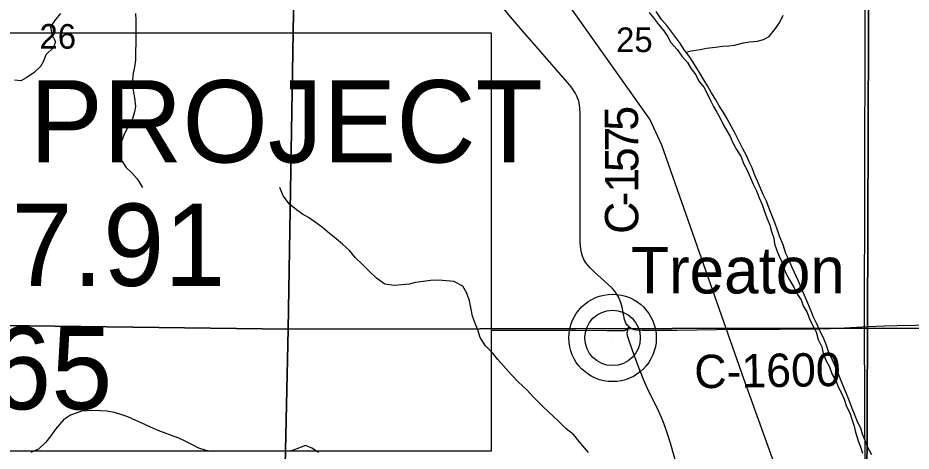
# Model space of a CAD drawing. Extents: x 0 to 34, y 0 to 22.
# Drawn here: x 17.64 to 19.16, y 14.964 to 15.701 of the extents above; entities that cross this region are included whole.
import ezdxf

# ---------------------------------------------------------------- set-up
doc = ezdxf.new("R2010")
doc.units = 0
for name, color, linetype in [('GM_X_County_Road', 7, 'Continuous'), ('GM_X_County_Road_Text', 7, 'Continuous'), ('GM_X_Major_River', 7, 'Continuous'), ('GM_X_Minor_River', 7, 'Continuous'), ('GM_X_Rail_Line', 7, 'Continuous'), ('GM_X_Section', 7, 'Continuous'), ('GM_X_Section_Text', 7, 'Continuous'), ('GM_X_Township_Road', 7, 'Continuous'), ('GM_X_Unincorporated', 7, 'Continuous'), ('GM_X_Unincorporated_Location', 7, 'Continuous'), ('GM_X_Unincorporated_Text', 7, 'Continuous'), ('GM_X_US_Shield', 7, 'Continuous'), ('SH_Text', 7, 'Continuous')]:
    doc.layers.add(name, color=color, linetype=linetype)

msp = doc.modelspace()

# ---------------------------------------------------------------- linework, layer by layer
at = {"layer": 'GM_X_County_Road'}
for points in [[(18.6801, 15.1752), (18.6769, 15.1782), (18.6747, 15.1812), (18.6733, 15.1847), (18.6726, 15.1876), (18.6707, 15.1967), (18.6681, 15.2089), (18.6665, 15.2148), (18.6645, 15.2206), (18.6619, 15.2262), (18.6588, 15.2314), (18.6552, 15.2363), (18.6511, 15.2409), (18.6444, 15.2473), (18.6213, 15.2681), (18.6146, 15.2747), (18.6103, 15.2793), (18.6065, 15.2843), (18.6048, 15.287), (18.6032, 15.2897), (18.6018, 15.2926), (18.6007, 15.2955), (18.599, 15.3016), (18.5978, 15.3078), (18.597, 15.3184), (18.5969, 15.3261), (18.5968, 15.3359), (18.5968, 15.3488), (18.5968, 15.3607), (18.5968, 15.37), (18.5967, 15.3948), (18.5969, 15.4228), (18.5969, 15.4508), (18.5967, 15.4819), (18.5971, 15.5253), (18.5968, 15.5377), (18.5963, 15.547), (18.5956, 15.5531), (18.5944, 15.5591), (18.5935, 15.562), (18.5912, 15.5677), (18.5884, 15.5731), (18.5852, 15.5784), (18.5816, 15.5834), (18.5757, 15.5905), (18.5634, 15.6044), (18.5226, 15.6514), (18.5022, 15.6748), (18.4819, 15.6984), (18.4578, 15.7268)], [(19.0861, 15.1755), (19.1151, 15.1769), (19.1368, 15.1775), (19.1679, 15.1781), (19.1866, 15.1784), (19.2239, 15.1785), (19.2425, 15.1784), (19.286, 15.1781), (19.3202, 15.1776), (19.3886, 15.1766), (19.4477, 15.1761), (19.5782, 15.1751), (19.6217, 15.1747), (19.6435, 15.1744), (19.6838, 15.1737), (19.718, 15.1739)], [(18.6801, 15.1752), (18.6841, 15.1726), (18.6885, 15.1709), (18.6923, 15.1701), (18.7023, 15.1694), (18.7185, 15.1695), (18.7613, 15.1694), (18.7955, 15.1698), (18.8288, 15.1704), (18.8857, 15.1711), (18.9158, 15.1714), (18.937, 15.1714), (18.9566, 15.1717), (19.0033, 15.172), (19.022, 15.1724), (19.0468, 15.1734), (19.0778, 15.1751), (19.0861, 15.1755)]]:
    msp.add_lwpolyline(points, dxfattribs=at)
at = {"layer": 'GM_X_Major_River'}
for points in [[(18.7142, 15.7102), (18.7218, 15.7007), (18.73, 15.6896), (18.7391, 15.6789), (18.7459, 15.6686), (18.7515, 15.6591), (18.762, 15.6473), (18.77, 15.6359), (18.7794, 15.6248), (18.7858, 15.6142), (18.7937, 15.6039), (18.7989, 15.5932), (18.808, 15.5825), (18.8188, 15.5605), (18.8241, 15.5502), (18.8297, 15.5403), (18.835, 15.53), (18.8406, 15.5193), (18.8466, 15.5087), (18.8523, 15.4988), (18.8568, 15.4885), (18.8631, 15.4767), (18.8707, 15.4642), (18.8748, 15.4531), (18.8804, 15.4428), (18.8868, 15.4288), (18.8916, 15.4177), (18.8973, 15.4067), (18.9014, 15.3945), (18.9066, 15.3835), (18.9104, 15.3732), (18.9149, 15.3607), (18.9197, 15.3481), (18.9227, 15.3375), (18.9264, 15.3261), (18.9279, 15.3166), (18.9316, 15.3048), (18.9354, 15.2953), (18.9402, 15.2858), (18.9432, 15.2763), (18.9477, 15.2656), (18.953, 15.255), (18.9612, 15.2416), (18.9661, 15.231), (18.9729, 15.2211), (18.9766, 15.2108), (18.9834, 15.1994), (18.9875, 15.1887), (18.9924, 15.1781), (18.9988, 15.1667), (19.0021, 15.1537), (19.0081, 15.1412), (19.0107, 15.1298), (19.0152, 15.1184), (19.0216, 15.107), (19.0257, 15.094), (19.0328, 15.0826), (19.0362, 15.0731), (19.0414, 15.0636), (19.0463, 15.0522), (19.0504, 15.0396), (19.0557, 15.029), (19.0594, 15.0179), (19.0631, 15.0062), (19.0657, 14.9959), (19.0702, 14.9811), (19.0739, 14.9708), (19.0773, 14.9605)], [(19.0934, 14.9572), (19.0865, 14.9697), (19.0831, 14.9792), (19.0778, 14.9928), (19.0747, 15.0027), (19.0693, 15.0137), (19.0651, 15.0239), (19.0598, 15.0364), (19.0541, 15.0516), (19.0491, 15.0641), (19.0449, 15.0747), (19.0392, 15.0891), (19.0331, 15.1035), (19.0262, 15.1186), (19.0197, 15.133), (19.0155, 15.1451), (19.0105, 15.1577), (19.0056, 15.1675), (18.9991, 15.1815), (18.9941, 15.1917), (18.9903, 15.2016), (18.9842, 15.2152), (18.9788, 15.2285), (18.9735, 15.2402), (18.9685, 15.2528), (18.9571, 15.277), (18.9521, 15.2899), (18.9471, 15.3001), (18.9422, 15.3145), (18.9364, 15.3293), (18.9326, 15.3399), (18.9288, 15.3509), (18.923, 15.3649), (18.9185, 15.3767), (18.9139, 15.3888), (18.9081, 15.4013), (18.9039, 15.4111), (18.8986, 15.4229), (18.8936, 15.4346), (18.8898, 15.4456), (18.8848, 15.4559), (18.8803, 15.4665), (18.8738, 15.4778), (18.8665, 15.4926), (18.8612, 15.5032), (18.8543, 15.5157), (18.8471, 15.529), (18.841, 15.5396), (18.8337, 15.5513), (18.8276, 15.5612), (18.8204, 15.5733), (18.8135, 15.585), (18.8074, 15.5956), (18.8002, 15.6077), (18.7914, 15.6214), (18.7823, 15.6354), (18.7747, 15.6456), (18.7663, 15.6585), (18.7564, 15.6721), (18.7442, 15.688), (18.7354, 15.6978), (18.7263, 15.7115)]]:
    msp.add_lwpolyline(points, dxfattribs=at)
at = {"layer": 'GM_X_Minor_River'}
for points in [[(17.7124, 15.7083), (17.7037, 15.6981), (17.695, 15.6859), (17.6973, 15.6719), (17.7034, 15.6609), (17.7, 15.6503), (17.6872, 15.6377), (17.683, 15.6274), (17.6781, 15.6179), (17.6675, 15.608), (17.655, 15.5993), (17.6444, 15.5936), (17.6338, 15.595)], [(17.8398, 15.7084), (17.8406, 15.697), (17.8407, 15.6712), (17.8403, 15.6571), (17.84, 15.6439), (17.8397, 15.6291), (17.8382, 15.6177), (17.8359, 15.6067), (17.8341, 15.59), (17.836, 15.5771), (17.8383, 15.5649), (17.8399, 15.5501), (17.8384, 15.5407), (17.835, 15.5289), (17.826, 15.5141), (17.8199, 15.5015), (17.8158, 15.4901), (17.8139, 15.478), (17.8151, 15.4658), (17.817, 15.4564), (17.8239, 15.4465), (17.8338, 15.4371), (17.8425, 15.4268), (17.8517, 15.4125)], [(18.777, 15.6424), (18.786, 15.6449), (18.8012, 15.6468), (18.8122, 15.6491), (18.8274, 15.6511), (18.8391, 15.6526), (18.8501, 15.6534), (18.8596, 15.6546), (18.8748, 15.6581), (18.8854, 15.66), (18.8987, 15.6612), (18.9089, 15.6639), (18.9187, 15.6692), (18.9297, 15.6825), (18.9361, 15.6924), (18.9425, 15.7057)], [(18.6109, 14.9614), (18.598, 14.9765), (18.5858, 14.9917), (18.5732, 15.0019), (18.5607, 15.014), (18.5508, 15.0231), (18.534, 15.039), (18.5181, 15.0548), (18.5063, 15.0677), (18.4918, 15.0813), (18.4796, 15.0942), (18.4663, 15.1089), (18.4568, 15.1195), (18.4481, 15.1305), (18.4355, 15.143), (18.4267, 15.157), (18.4229, 15.1699), (18.4187, 15.1797), (18.4137, 15.1934), (18.4114, 15.2051), (18.4087, 15.2192), (18.4041, 15.2324), (18.3969, 15.2442), (18.3817, 15.2521), (18.3692, 15.2532), (18.3555, 15.2543), (18.3422, 15.2542), (18.3297, 15.2523), (18.3165, 15.2504), (18.3055, 15.2477), (18.2933, 15.2465), (18.2801, 15.2453), (18.2641, 15.2475), (18.2504, 15.2581), (18.2383, 15.2691), (18.2261, 15.2812), (18.2143, 15.2925), (18.2044, 15.305), (18.1922, 15.316), (18.1816, 15.3247), (18.1702, 15.3341), (18.1584, 15.344), (18.1458, 15.3534), (18.1344, 15.3613), (18.1242, 15.367), (18.1139, 15.3742), (18.1021, 15.3836), (18.0911, 15.398), (18.0857, 15.412)], [(17.971, 14.9632), (17.96, 14.9647), (17.9478, 14.9688), (17.936, 14.9749), (17.9235, 14.9813), (17.9136, 14.9858), (17.8996, 14.9911), (17.8878, 14.9952), (17.8783, 14.9986), (17.8654, 15.0043), (17.8532, 15.0103), (17.8407, 15.0159), (17.8267, 15.022), (17.8168, 15.0257), (17.8039, 15.0295), (17.7913, 15.0317), (17.78, 15.0321), (17.7671, 15.0328), (17.7576, 15.0324), (17.7481, 15.0316), (17.7386, 15.0285), (17.7292, 15.0251), (17.7174, 15.0167), (17.7034, 15.0011), (17.6959, 14.9897), (17.6872, 14.9787), (17.6747, 14.9672), (17.6614, 14.9615)], [(18.1512, 14.9615), (18.1398, 14.9687), (18.1295, 14.9732), (18.1147, 14.9675), (18.1018, 14.9633)]]:
    msp.add_lwpolyline(points, dxfattribs=at)
at = {"layer": 'GM_X_Rail_Line'}
for points in [[(19.082, 14.1642), (19.0858, 15.176), (19.0896, 16.1806), (19.0934, 17.1717), (19.0972, 18.1277), (19.0975, 18.2511), (19.0976, 18.2716), (19.1032, 19.1112), (19.1046, 20.1073), (19.105, 20.2214), (18.9873, 20.2214), (18.4948, 20.2275), (17.7586, 20.2281), (16.9636, 20.2311)], [(19.1602, 14.2954), (18.8757, 15.0866), (18.7358, 15.4844), (18.7152, 15.5285), (18.5866, 15.7098), (18.3527, 16.0317), (18.2813, 16.1295), (18.2071, 16.1856), (18.119, 16.2347), (17.9168, 16.34), (17.6261, 16.4909)]]:
    msp.add_lwpolyline(points, dxfattribs=at)
msp.add_lwpolyline([(20.0404, 14.169), (20.0404, 20.2202), (19.5489, 20.2208), (19.5137, 20.2208), (19.105, 20.2214), (19.1046, 20.1073), (19.1032, 19.1112), (19.0976, 18.2716), (19.0975, 18.2511), (19.0972, 18.1277), (19.0934, 17.1717), (19.0896, 16.1806), (19.0858, 15.176), (19.082, 14.1642)], close=True, dxfattribs=at)
at = {"layer": 'GM_X_Section'}
for points in [[(17.0958, 16.189), (18.1169, 16.1822), (18.0996, 15.1714), (17.0854, 15.1843)], [(19.0829, 16.1788), (19.0804, 15.1729), (18.0996, 15.1714), (18.1169, 16.1822)], [(17.0854, 15.1843), (18.0996, 15.1714), (18.0777, 14.1666), (17.1558, 14.1702), (17.0728, 14.1742)], [(18.0996, 15.1714), (19.0804, 15.1729), (19.0847, 14.1682), (18.1505, 14.1672), (18.0777, 14.1666)]]:
    msp.add_lwpolyline(points, close=True, dxfattribs=at)
at = {"layer": 'GM_X_Township_Road'}
for points in [[(18.4454, 15.1696), (18.4466, 15.1695), (18.4745, 15.1694), (18.5429, 15.1693), (18.5894, 15.1693), (18.6424, 15.1689), (18.6534, 15.1691), (18.6648, 15.169), (18.6722, 15.1692), (18.675, 15.1704), (18.6778, 15.1723), (18.6801, 15.1752)], [(18.7645, 14.9293), (18.7505, 14.977), (18.7449, 14.9947), (18.7398, 15.0093), (18.7352, 15.0208), (18.7301, 15.0321), (18.7112, 15.0713), (18.7049, 15.0855), (18.6944, 15.1115), (18.6857, 15.1348), (18.6791, 15.1545), (18.6776, 15.1599), (18.6769, 15.164), (18.6773, 15.168), (18.6784, 15.1715), (18.6801, 15.1752)]]:
    msp.add_lwpolyline(points, dxfattribs=at)
at = {"layer": 'GM_X_Unincorporated'}
for radius in [0.0744, 0.0472]:
    msp.add_circle((18.652, 15.1563), radius, dxfattribs=at)
at = {"layer": 'GM_X_Unincorporated_Location'}
msp.add_line((18.652, 15.1563), (18.652, 15.1563), dxfattribs=at)
at = {"layer": 'GM_X_US_Shield'}
for points in [[(20.0404, 15.1674), (20.0404, 16.173), (19.0829, 16.1788), (19.0804, 15.1729)], [(20.0404, 14.1653), (20.0404, 15.1674), (19.0804, 15.1729), (19.0847, 14.1682)]]:
    msp.add_lwpolyline(points, close=True, dxfattribs=at)
at = {"layer": 'SH_Text'}
msp.add_lwpolyline([(16.657, 15.6754), (18.4454, 15.6754), (18.4454, 14.9637), (16.657, 14.9637)], close=True, dxfattribs=at)

# ---------------------------------------------------------------- texts
at = {"layer": 'GM_X_County_Road_Text'}
for s, height, rotation, p in [('5', 0.0568, 90.7268, (18.6957, 15.5091)), ('7', 0.0568, 90.2011, (18.6959, 15.4736)), ('5', 0.0568, 90.0458, (18.6959, 15.4384)), ('1', 0.0568, 90.0079, (18.6959, 15.4034)), ('-', 0.0568, 90, (18.6959, 15.38)), ('C', 0.0568, 90, (18.6959, 15.3333)), ('C-1600', 0.05682, 0.9186, (18.7916, 15.0705))]:
    msp.add_text(s, height=height, rotation=rotation, dxfattribs=at).set_placement(p)
at = {"layer": 'GM_X_Section_Text'}
for s, p in [('26', (17.6764, 15.6484)), ('25', (18.658, 15.6426))]:
    msp.add_text(s, height=0.04186, rotation=0, dxfattribs=at).set_placement(p)
at = {"layer": 'GM_X_Unincorporated_Text'}
msp.add_text('Treaton', height=0.07898, rotation=0, dxfattribs=at).set_placement((18.6835, 15.232))
at = {"layer": 'SH_Text'}
for s, p in [('SUSPEND PROJECT', (16.7025, 15.4548)), ('ASD-250-17.91', (16.7025, 15.2448)), ('STA. 945+65', (16.7025, 15.0348))]:
    msp.add_text(s, height=0.14, dxfattribs=at).set_placement(p)

doc.saveas('drawing.dxf')
